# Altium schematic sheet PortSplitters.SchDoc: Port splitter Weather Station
size A; Organization: Altium Limited; Address1: L3, 12a Rodborough Rd; Address2: Frenchs Forest; Address3: NSW; Address4: Australia 2086; DocumentNumber: 2; SheetNumber: 2; SheetTotal: 2
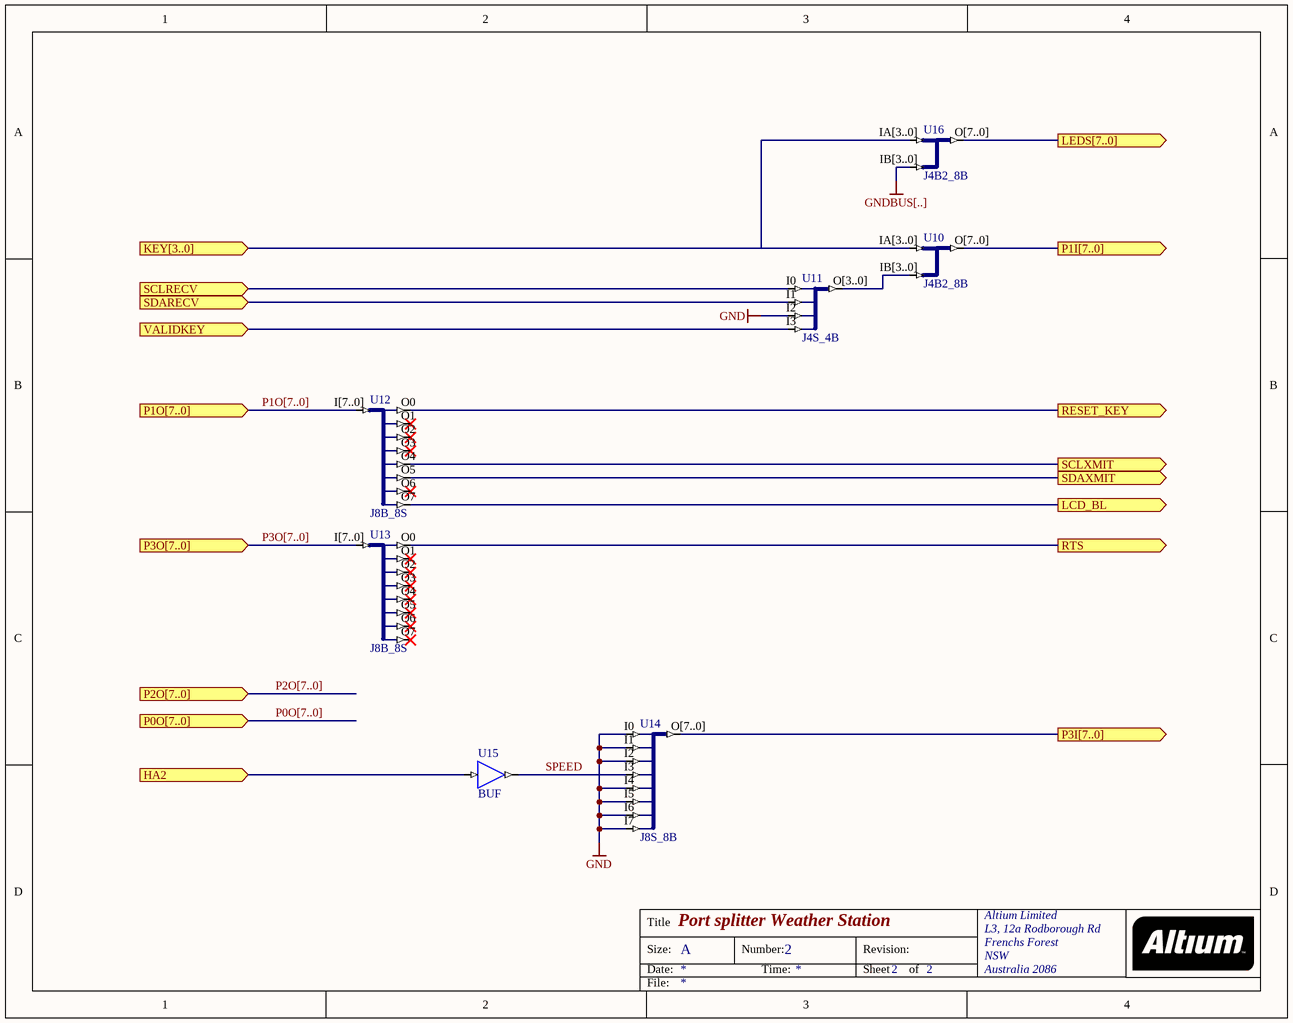
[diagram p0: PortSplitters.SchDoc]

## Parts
U10  J4B2_8B
U11  J4S_4B
U12  J8B_8S
U13  J8B_8S
U14  J8S_8B
U15  BUF
U16  J4B2_8B

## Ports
HA2 (in), KEY[3..0] (in), LCD_BL (out), LEDS[7..0] (out), P0O[7..0] (in), P1I[7..0] (out), P1O[7..0] (in), P2O[7..0] (in), P3I[7..0] (out), P3O[7..0] (in), RESET_KEY (out), RTS (out), SCLRECV (in), SCLXMIT (out), SDARECV (in), SDAXMIT (out), VALIDKEY (in)

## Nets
GND: U11.I2 U14.I0 U14.I1 U14.I2 U14.I4 U14.I5 U14.I6 U14.I7
HA2: U15.I ; port HA2
LCD_BL: U12.O7 ; port LCD_BL
RESET_KEY: U12.O0 ; port RESET_KEY
RTS: U13.O0 ; port RTS
SCLRECV: U11.I0 ; port SCLRECV
SCLXMIT: U12.O4 ; port SCLXMIT
SDARECV: U11.I1 ; port SDARECV
SDAXMIT: U12.O5 ; port SDAXMIT
SPEED: U14.I3 U15.O
VALIDKEY: U11.I3 ; port VALIDKEY

Not connected (* = marked no-connect by the designer): U10 IA[3..0] IB[3..0] O[7..0]; U11 O[3..0]; U12 I[7..0] O1* O2* O3* O6*; U13 I[7..0] O1* O2* O3* O4* O5* O6* O7*; U14 O[7..0]; U16 IA[3..0] IB[3..0] O[7..0]

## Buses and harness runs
bus P0O[7..0] = port P0O[7..0]
bus P1O[7..0] = port P1O[7..0]
bus P2O[7..0] = port P2O[7..0]
bus P3O[7..0] = port P3O[7..0]

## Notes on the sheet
- Labels drawn without touching a wire or pin: GNDBUS[..]

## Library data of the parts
U10 = J4B2_8B: 2 x 4-Bit input bus to 1 x 8-bit output bus; ArchiveName: GENERIC
U11 = J4S_4B: 4 Single pin inputs to single 4-Bit output bus; ArchiveName: GENERIC
U12 U13 = J8B_8S: 8-Bit input bus to 8 single pin outputs; ArchiveName: GENERIC
U14 = J8S_8B: 8 Single pin inputs to single 8-Bit output bus; ArchiveName: GENERIC
U15 = BUF: 1-bit General Purpose (Non-inverting) Buffer; ArchiveName: GENERIC
U16 = J4B2_8B: 2 x 4-Bit input bus to 1 x 8-bit output bus; ArchiveName: GENERIC; VHDLIB_SIM: GENERIC_LIB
